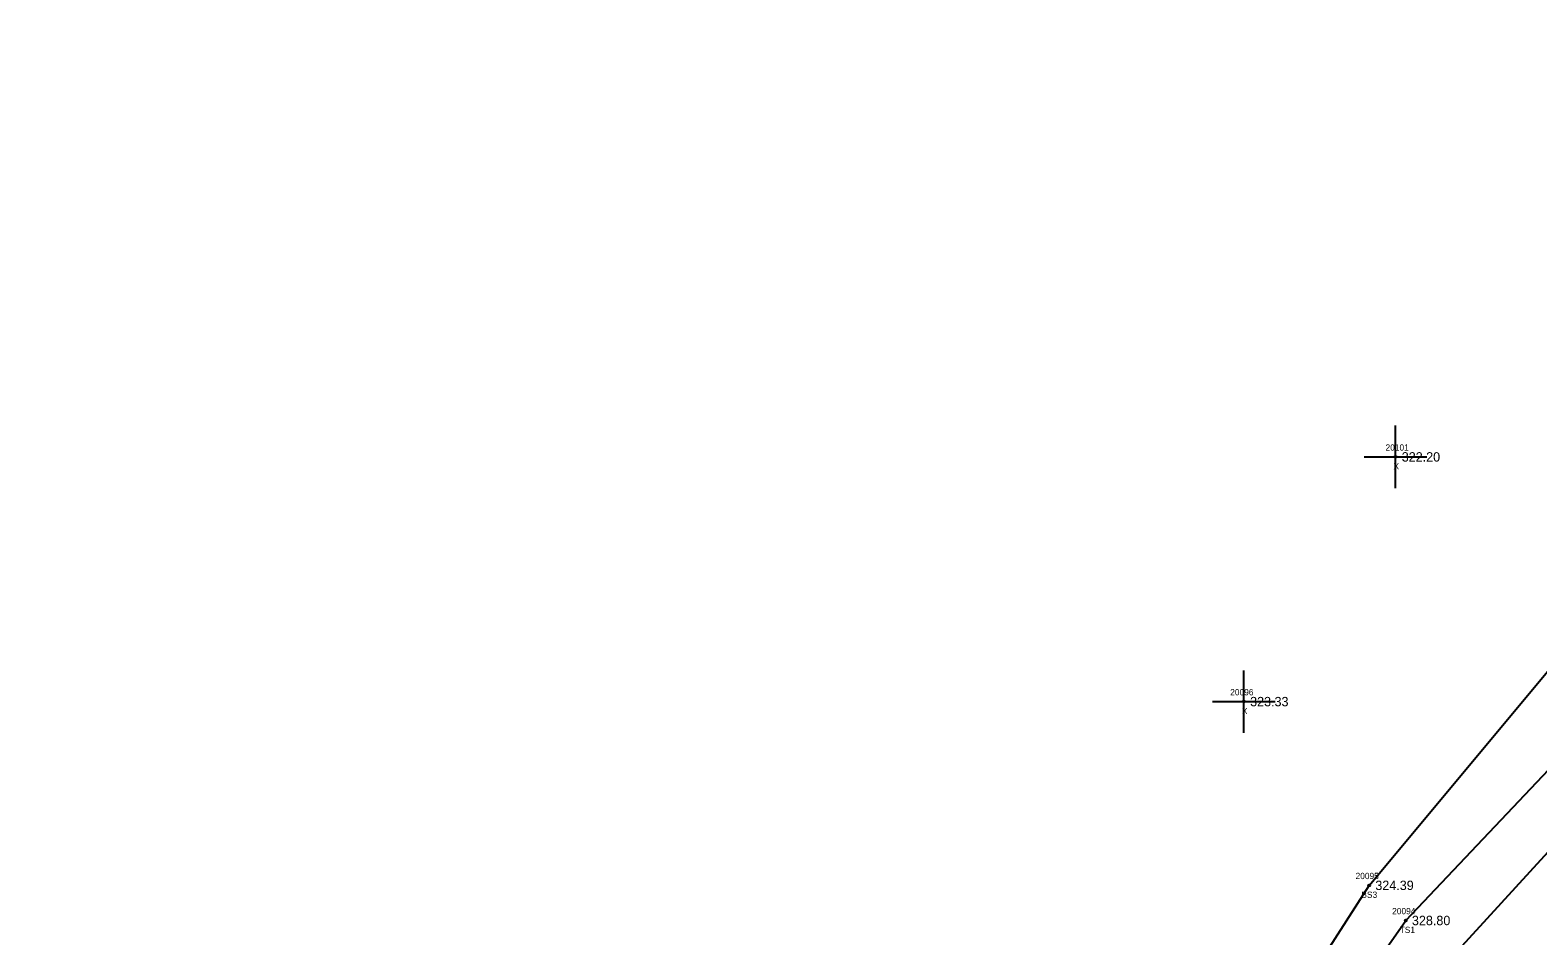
# Model space of a CAD drawing. Extents: x 2231109 to 2232328, y 1035718 to 1036919.
# Drawn here: x 2231153.9 to 2231394.8, y 1036302.1 to 1036446.9 of the extents above; entities that cross this region are included whole.
import ezdxf

# ---------------------------------------------------------------- set-up
doc = ezdxf.new("R2010")
doc.units = 0
for name, color, linetype in [('RD_DTM_BkLn2', 7, 'Continuous'), ('RD_DTM_BkLn_txCode', 7, 'Continuous'), ('RD_EX_Misc', 7, 'Continuous'), ('RD_EX_Misc_txCode', 7, 'Continuous'), ('RD_EX_Road', 7, 'Continuous'), ('RD_EX_TX_Misc_ELEV', 7, 'Continuous'), ('RD_SMD_Locator', 7, 'Continuous')]:
    doc.layers.add(name, color=color, linetype=linetype)

msp = doc.modelspace()

# ---------------------------------------------------------------- linework, layer by layer
at = {"layer": 'RD_DTM_BkLn2'}
for points in [[(2231289.28, 1036185.01), (2231310.58, 1036229.41), (2231341.66, 1036269.31), (2231367.87, 1036310.22), (2231401.74, 1036350.83), (2231444.02, 1036383.07), (2231489.16, 1036422.11), (2231530.24, 1036446.93), (2231543.7, 1036441.83)], [(2231153.91, 1035749.54), (2231183.9, 1035852.41), (2231210.94, 1035948.08), (2231242.08, 1036041.75), (2231274.33, 1036134.79), (2231295.17, 1036181.88), (2231317.55, 1036225.12), (2231346.22, 1036265.16), (2231373.72, 1036304.6), (2231409.94, 1036342.78), (2231447.25, 1036376.56), (2231493.69, 1036413.26), (2231528.08, 1036438.61), (2231532.84, 1036438.24), (2231534.71, 1036436.33)]]:
    msp.add_lwpolyline(points, dxfattribs=at)
at = {"layer": 'RD_EX_Misc'}
for p, q in [((2231372.09, 1036373.71), (2231372.09, 1036383.71)), ((2231367.09, 1036378.71), (2231377.09, 1036378.71)), ((2231347.86, 1036334.59), (2231347.86, 1036344.59)), ((2231342.86, 1036339.59), (2231352.86, 1036339.59))]:
    msp.add_line(p, q, dxfattribs=at)
at = {"layer": 'RD_EX_Road'}
msp.add_lwpolyline([(2231158.42, 1035748.11), (2231188.37, 1035851.38), (2231216.59, 1035946.92), (2231244.77, 1036040.72), (2231278.59, 1036133.31), (2231299.55, 1036179.73), (2231323.11, 1036221.2), (2231350.7, 1036262.3), (2231381.59, 1036299.29), (2231415.97, 1036336.9), (2231452.94, 1036369.74), (2231498.19, 1036405.3), (2231537.2, 1036432.57), (2231541.46, 1036424.96)], dxfattribs=at)
at = {"layer": 'RD_SMD_Locator'}
for centre in [(2231372.09, 1036378.71), (2231347.86, 1036339.59), (2231367.87, 1036310.22), (2231373.72, 1036304.6)]:
    msp.add_circle(centre, 0.15, dxfattribs=at)

# ---------------------------------------------------------------- texts
at = {"layer": 'RD_DTM_BkLn_txCode'}
for s, p in [('20095', (2231365.71, 1036311.22)), ('BS3', (2231366.64, 1036308.22)), ('20094', (2231371.56, 1036305.6)), ('TS1', (2231372.76, 1036302.6))]:
    msp.add_text(s, height=1, dxfattribs=at).set_placement(p)
at = {"layer": 'RD_EX_Misc_txCode'}
for s, p in [('20101', (2231370.5, 1036379.71)), ('X', (2231371.77, 1036376.71)), ('20096', (2231345.68, 1036340.59)), ('X', (2231347.55, 1036337.59))]:
    msp.add_text(s, height=1, dxfattribs=at).set_placement(p)
at = {"layer": 'RD_EX_TX_Misc_ELEV'}
for s, p in [('322.20', (2231373.09, 1036377.96)), ('323.33', (2231348.86, 1036338.84)), ('324.39', (2231368.87, 1036309.47)), ('328.80', (2231374.72, 1036303.85))]:
    msp.add_text(s, height=1.5, dxfattribs=at).set_placement(p)

doc.saveas('drawing.dxf')
